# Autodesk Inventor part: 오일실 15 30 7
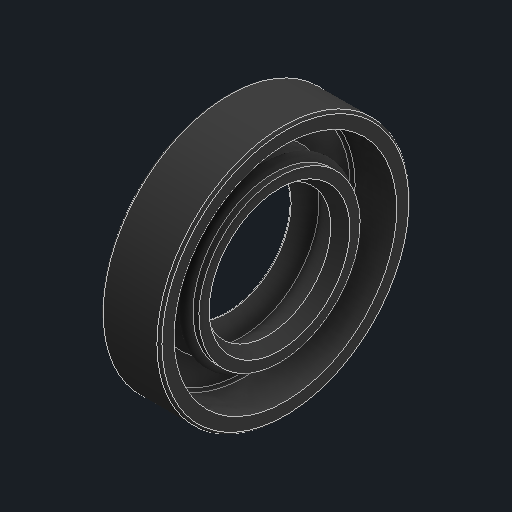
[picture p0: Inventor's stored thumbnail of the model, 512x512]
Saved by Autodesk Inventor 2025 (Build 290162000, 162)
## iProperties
Created: 2025-08
Part Number: 오일실 15 30 7
Material: 고무
Description: 오일-실
Document SubType Name: Modeling
Designer: infra002
Density: 0.93 g/cm^3
Appearance: 기본값
Author: jhkim
Sending System: Autodesk Inventor 2026
Preprocessor: ST-DEVELOPER v20.1
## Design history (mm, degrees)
feature "Solid1"
node "솔리드1"
